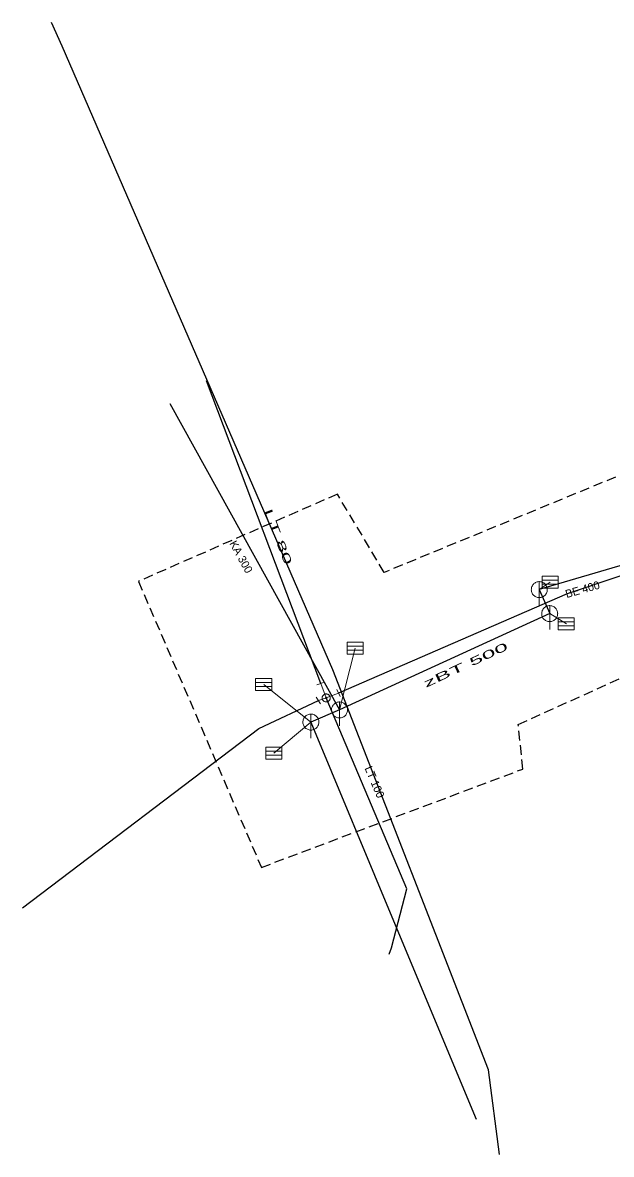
# Model space of a CAD drawing. Extents: x -687387 to -687009, y -972789 to -972578.
# Drawn here: x -687387 to -687313.5, y -972784 to -972642.7 of the extents above; entities that cross this region are included whole.
import ezdxf

# ---------------------------------------------------------------- set-up
doc = ezdxf.new("R2010")
doc.units = 0
doc.header["$LTSCALE"] = 0.4
doc.linetypes.add('MEDIUM_DASHED', pattern=[4.5, 3, -1.5])
doc.layers.add('1', color=7, linetype='Continuous')
for name, color, linetype, lineweight in [('11', 7, 'Continuous', 13), ('14', 7, 'Continuous', 25), ('17', 7, 'Continuous', 25), ('22', 7, 'Continuous', 13), ('34', 7, 'Continuous', 13), ('47', 7, 'Continuous', 13), ('63', 7, 'MEDIUM_DASHED', 25)]:
    doc.layers.add(name, color=color, linetype=linetype, lineweight=lineweight)

msp = doc.modelspace()

# ---------------------------------------------------------------- linework, layer by layer
at = {"layer": '11'}
for p, q in [((-687321.129, -972712.545), (-687322.482, -972713.486)), ((-687319.098, -972717.753), (-687321.188, -972716.487)), ((-687345.471, -972720.82), (-687347.44, -972728.52)), ((-687356.905, -972725.343), (-687351.02, -972730.03)), ((-687355.64, -972733.905), (-687351.02, -972730.03))]:
    msp.add_line(p, q, dxfattribs=at)
at = {"layer": '14'}
for p, q in [((-687368.649, -972690.243), (-687347.44, -972728.52)), ((-687311, -972710.109), (-687322.482, -972713.486)), ((-687322.482, -972713.486), (-687321.188, -972716.487)), ((-687321.188, -972716.487), (-687347.44, -972728.52)), ((-687347.44, -972728.52), (-687351.02, -972730.03))]:
    msp.add_line(p, q, dxfattribs=at)
at = {"layer": '14', "lineweight": 13}
msp.add_line((-687349.109, -972727.02), (-687347.571, -972726.403), dxfattribs=at)
msp.add_lwpolyline([(-687350.08, -972727.344), (-687349.109, -972727.02), (-687349.785, -972725.226)], dxfattribs=at)
at = {"layer": '14'}
msp.add_lwpolyline([(-687351.02, -972730.03), (-687340.476, -972755.348), (-687330.362, -972779.636)], dxfattribs=at)
at = {"layer": '17'}
msp.add_line((-687349.785, -972725.226), (-687364.052, -972687.396), dxfattribs=at)
for points in [[(-687327.469, -972784.025), (-687328.848, -972773.48), (-687348.283, -972723.514), (-687382.078, -972645.626), (-687383.429, -972642.673)], [(-687288.604, -972703.811), (-687319.02, -972714.015), (-687347.571, -972726.403)], [(-687387.027, -972753.222), (-687357.518, -972730.819), (-687350.08, -972727.344)], [(-687341.227, -972759.019), (-687340.943, -972758.234), (-687339.032, -972750.864), (-687349.109, -972727.02)]]:
    msp.add_lwpolyline(points, dxfattribs=at)
at = {"layer": '22'}
for p, q in [((-687322.14, -972712.288), (-687320.14, -972712.288)), ((-687322.482, -972715.486), (-687322.481, -972712.486)), ((-687322.14, -972712.788), (-687320.14, -972712.788)), ((-687321.188, -972718.487), (-687321.187, -972715.487)), ((-687320.109, -972717.496), (-687318.109, -972717.496)), ((-687320.109, -972717.996), (-687318.109, -972717.996)), ((-687346.482, -972720.563), (-687344.482, -972720.563)), ((-687346.482, -972721.063), (-687344.482, -972721.063)), ((-687357.916, -972725.086), (-687355.916, -972725.086)), ((-687357.916, -972725.586), (-687355.916, -972725.586)), ((-687347.44, -972730.52), (-687347.439, -972727.52)), ((-687351.02, -972732.03), (-687351.019, -972729.03)), ((-687356.651, -972733.648), (-687354.651, -972733.648)), ((-687356.651, -972734.148), (-687354.651, -972734.148))]:
    msp.add_line(p, q, dxfattribs=at)
for points in [[(-687322.14, -972711.788), (-687320.14, -972711.788), (-687320.14, -972713.288), (-687322.14, -972713.288)], [(-687321.482, -972713.486), (-687321.487, -972713.377), (-687321.505, -972713.269), (-687321.535, -972713.163), (-687321.575, -972713.062), (-687321.627, -972712.965), (-687321.689, -972712.875), (-687321.761, -972712.792), (-687321.841, -972712.718), (-687321.929, -972712.652), (-687322.023, -972712.597), (-687322.123, -972712.552), (-687322.228, -972712.519), (-687322.335, -972712.497), (-687322.444, -972712.487), (-687322.554, -972712.489), (-687322.662, -972712.503), (-687322.769, -972712.528), (-687322.872, -972712.565), (-687322.97, -972712.614), (-687323.062, -972712.672), (-687323.148, -972712.741), (-687323.225, -972712.818), (-687323.294, -972712.904), (-687323.353, -972712.996), (-687323.401, -972713.094), (-687323.438, -972713.197), (-687323.464, -972713.304), (-687323.478, -972713.412), (-687323.481, -972713.522), (-687323.471, -972713.631), (-687323.45, -972713.738), (-687323.416, -972713.842), (-687323.372, -972713.942), (-687323.317, -972714.037), (-687323.251, -972714.125), (-687323.177, -972714.205), (-687323.094, -972714.277), (-687323.004, -972714.339), (-687322.908, -972714.391), (-687322.806, -972714.432), (-687322.701, -972714.462), (-687322.593, -972714.48), (-687322.483, -972714.486), (-687322.374, -972714.48), (-687322.266, -972714.462), (-687322.161, -972714.433), (-687322.059, -972714.392), (-687321.962, -972714.34), (-687321.872, -972714.278), (-687321.789, -972714.207), (-687321.714, -972714.127), (-687321.649, -972714.039), (-687321.593, -972713.945), (-687321.549, -972713.845), (-687321.515, -972713.741), (-687321.493, -972713.633), (-687321.483, -972713.524)], [(-687320.188, -972716.487), (-687320.193, -972716.378), (-687320.211, -972716.27), (-687320.241, -972716.164), (-687320.281, -972716.063), (-687320.333, -972715.966), (-687320.395, -972715.876), (-687320.467, -972715.793), (-687320.547, -972715.719), (-687320.635, -972715.653), (-687320.729, -972715.598), (-687320.829, -972715.553), (-687320.934, -972715.52), (-687321.041, -972715.498), (-687321.15, -972715.488), (-687321.26, -972715.49), (-687321.368, -972715.504), (-687321.475, -972715.529), (-687321.578, -972715.566), (-687321.676, -972715.615), (-687321.768, -972715.673), (-687321.854, -972715.742), (-687321.931, -972715.819), (-687322, -972715.905), (-687322.059, -972715.997), (-687322.107, -972716.095), (-687322.144, -972716.198), (-687322.17, -972716.305), (-687322.184, -972716.413), (-687322.187, -972716.523), (-687322.177, -972716.632), (-687322.156, -972716.739), (-687322.122, -972716.843), (-687322.078, -972716.943), (-687322.023, -972717.038), (-687321.957, -972717.126), (-687321.883, -972717.206), (-687321.8, -972717.278), (-687321.71, -972717.34), (-687321.614, -972717.392), (-687321.512, -972717.433), (-687321.407, -972717.463), (-687321.299, -972717.481), (-687321.189, -972717.487), (-687321.08, -972717.481), (-687320.972, -972717.463), (-687320.867, -972717.434), (-687320.765, -972717.393), (-687320.668, -972717.341), (-687320.578, -972717.279), (-687320.495, -972717.208), (-687320.42, -972717.128), (-687320.355, -972717.04), (-687320.299, -972716.946), (-687320.255, -972716.846), (-687320.221, -972716.742), (-687320.199, -972716.634), (-687320.189, -972716.525)], [(-687320.109, -972716.996), (-687318.109, -972716.996), (-687318.109, -972718.496), (-687320.109, -972718.496)], [(-687346.482, -972720.063), (-687344.482, -972720.063), (-687344.482, -972721.563), (-687346.482, -972721.563)], [(-687357.916, -972724.586), (-687355.916, -972724.586), (-687355.916, -972726.086), (-687357.916, -972726.086)], [(-687346.44, -972728.52), (-687346.445, -972728.411), (-687346.463, -972728.303), (-687346.493, -972728.197), (-687346.533, -972728.096), (-687346.585, -972727.999), (-687346.647, -972727.909), (-687346.719, -972727.826), (-687346.799, -972727.752), (-687346.887, -972727.686), (-687346.981, -972727.631), (-687347.081, -972727.586), (-687347.186, -972727.553), (-687347.293, -972727.531), (-687347.402, -972727.521), (-687347.512, -972727.523), (-687347.62, -972727.537), (-687347.727, -972727.562), (-687347.83, -972727.599), (-687347.928, -972727.648), (-687348.02, -972727.706), (-687348.106, -972727.775), (-687348.183, -972727.852), (-687348.252, -972727.938), (-687348.311, -972728.03), (-687348.359, -972728.128), (-687348.396, -972728.231), (-687348.422, -972728.338), (-687348.436, -972728.446), (-687348.439, -972728.556), (-687348.429, -972728.665), (-687348.408, -972728.772), (-687348.374, -972728.876), (-687348.33, -972728.976), (-687348.275, -972729.071), (-687348.209, -972729.159), (-687348.135, -972729.239), (-687348.052, -972729.311), (-687347.962, -972729.373), (-687347.866, -972729.425), (-687347.764, -972729.466), (-687347.659, -972729.496), (-687347.551, -972729.514), (-687347.441, -972729.52), (-687347.332, -972729.514), (-687347.224, -972729.496), (-687347.119, -972729.467), (-687347.017, -972729.426), (-687346.92, -972729.374), (-687346.83, -972729.312), (-687346.747, -972729.241), (-687346.672, -972729.161), (-687346.607, -972729.073), (-687346.551, -972728.979), (-687346.507, -972728.879), (-687346.473, -972728.775), (-687346.451, -972728.667), (-687346.441, -972728.558)], [(-687350.02, -972730.03), (-687350.025, -972729.921), (-687350.043, -972729.813), (-687350.073, -972729.707), (-687350.113, -972729.606), (-687350.165, -972729.509), (-687350.227, -972729.419), (-687350.299, -972729.336), (-687350.379, -972729.262), (-687350.467, -972729.196), (-687350.561, -972729.141), (-687350.661, -972729.096), (-687350.766, -972729.063), (-687350.873, -972729.041), (-687350.982, -972729.031), (-687351.092, -972729.033), (-687351.2, -972729.047), (-687351.307, -972729.072), (-687351.41, -972729.109), (-687351.508, -972729.158), (-687351.6, -972729.216), (-687351.686, -972729.285), (-687351.763, -972729.362), (-687351.832, -972729.448), (-687351.891, -972729.54), (-687351.939, -972729.638), (-687351.976, -972729.741), (-687352.002, -972729.848), (-687352.016, -972729.956), (-687352.019, -972730.066), (-687352.009, -972730.175), (-687351.988, -972730.282), (-687351.954, -972730.386), (-687351.91, -972730.486), (-687351.855, -972730.581), (-687351.789, -972730.669), (-687351.715, -972730.749), (-687351.632, -972730.821), (-687351.542, -972730.883), (-687351.446, -972730.935), (-687351.344, -972730.976), (-687351.239, -972731.006), (-687351.131, -972731.024), (-687351.021, -972731.03), (-687350.912, -972731.024), (-687350.804, -972731.006), (-687350.699, -972730.977), (-687350.597, -972730.936), (-687350.5, -972730.884), (-687350.41, -972730.822), (-687350.327, -972730.751), (-687350.252, -972730.671), (-687350.187, -972730.583), (-687350.131, -972730.489), (-687350.087, -972730.389), (-687350.053, -972730.285), (-687350.031, -972730.177), (-687350.021, -972730.068)], [(-687356.651, -972733.148), (-687354.651, -972733.148), (-687354.651, -972734.648), (-687356.651, -972734.648)]]:
    msp.add_lwpolyline(points, close=True, dxfattribs=at)
at = {"layer": '34'}
for p, q in [((-687349.313, -972725.059), (-687350.256, -972725.391)), ((-687347.782, -972725.95), (-687347.359, -972726.856)), ((-687350.363, -972726.932), (-687349.797, -972727.756))]:
    msp.add_line(p, q, dxfattribs=at)
at = {"layer": '47'}
for points in [[(-687348.763, -972727.381), (-687348.728, -972727.343), (-687348.696, -972727.301), (-687348.669, -972727.257), (-687348.646, -972727.21), (-687348.629, -972727.16), (-687348.617, -972727.109), (-687348.611, -972727.057), (-687348.61, -972727.005), (-687348.613, -972726.953), (-687348.623, -972726.901), (-687348.638, -972726.851), (-687348.659, -972726.803), (-687348.683, -972726.757), (-687348.713, -972726.714), (-687348.747, -972726.674), (-687348.785, -972726.639), (-687348.827, -972726.607), (-687348.872, -972726.579), (-687348.918, -972726.557), (-687348.968, -972726.54), (-687349.019, -972726.528), (-687349.072, -972726.521), (-687349.124, -972726.52), (-687349.176, -972726.524), (-687349.227, -972726.534), (-687349.277, -972726.549), (-687349.326, -972726.569), (-687349.371, -972726.594), (-687349.414, -972726.624), (-687349.454, -972726.658), (-687349.489, -972726.696), (-687349.521, -972726.738), (-687349.549, -972726.782), (-687349.571, -972726.829), (-687349.588, -972726.879), (-687349.601, -972726.93), (-687349.608, -972726.982), (-687349.609, -972727.034), (-687349.604, -972727.087), (-687349.594, -972727.138), (-687349.579, -972727.188), (-687349.56, -972727.236), (-687349.534, -972727.282), (-687349.504, -972727.325), (-687349.47, -972727.365), (-687349.432, -972727.4), (-687349.39, -972727.432), (-687349.346, -972727.46), (-687349.299, -972727.482), (-687349.249, -972727.499), (-687349.198, -972727.512), (-687349.147, -972727.518), (-687349.094, -972727.519), (-687349.042, -972727.515), (-687348.99, -972727.505), (-687348.94, -972727.49), (-687348.892, -972727.47), (-687348.846, -972727.445), (-687348.803, -972727.415)], [(-687349.052, -972727.079), (-687349.045, -972727.073), (-687349.041, -972727.066), (-687349.037, -972727.059), (-687349.033, -972727.051), (-687349.03, -972727.043), (-687349.028, -972727.034), (-687349.027, -972727.026), (-687349.026, -972727.017), (-687349.028, -972727.009), (-687349.029, -972727), (-687349.031, -972726.992), (-687349.035, -972726.984), (-687349.039, -972726.977), (-687349.043, -972726.969), (-687349.049, -972726.963), (-687349.055, -972726.956), (-687349.062, -972726.952), (-687349.069, -972726.948), (-687349.077, -972726.944), (-687349.085, -972726.941), (-687349.094, -972726.939), (-687349.102, -972726.938), (-687349.111, -972726.937), (-687349.12, -972726.938), (-687349.128, -972726.94), (-687349.136, -972726.942), (-687349.144, -972726.946), (-687349.151, -972726.95), (-687349.159, -972726.954), (-687349.165, -972726.96), (-687349.172, -972726.966), (-687349.176, -972726.973), (-687349.18, -972726.98), (-687349.184, -972726.988), (-687349.187, -972726.996), (-687349.189, -972727.004), (-687349.19, -972727.013), (-687349.191, -972727.022), (-687349.19, -972727.031), (-687349.188, -972727.039), (-687349.186, -972727.047), (-687349.182, -972727.055), (-687349.178, -972727.062), (-687349.174, -972727.07), (-687349.168, -972727.076), (-687349.162, -972727.083), (-687349.155, -972727.087), (-687349.148, -972727.091), (-687349.14, -972727.095), (-687349.132, -972727.098), (-687349.124, -972727.1), (-687349.115, -972727.101), (-687349.106, -972727.102), (-687349.098, -972727.1), (-687349.089, -972727.099), (-687349.081, -972727.097), (-687349.073, -972727.093), (-687349.066, -972727.089), (-687349.058, -972727.085)]]:
    msp.add_lwpolyline(points, close=True, dxfattribs=at)
at = {"layer": '63'}
msp.add_lwpolyline([(-687147.303, -972666.399), (-687234.11, -972667.795), (-687234.11, -972667.795), (-687256.998, -972673.098), (-687256.998, -972673.098), (-687289.655, -972689.845), (-687289.655, -972689.845), (-687341.85, -972711.338), (-687341.85, -972711.338), (-687347.712, -972701.568), (-687347.712, -972701.568), (-687372.554, -972712.454), (-687357.202, -972748.182), (-687357.202, -972748.182), (-687324.545, -972735.9), (-687324.545, -972735.9), (-687325.103, -972730.318), (-687325.103, -972730.318), (-687291.05, -972714.966), (-687291.05, -972714.966), (-687198.94, -972690.124), (-687198.94, -972690.124), (-687142.558, -972685.938)], dxfattribs=at)

# ---------------------------------------------------------------- texts
at = {"layer": '1'}
for s, rotation, width, p in [('LT 80 ', 291, 2.15, (-687356.879, -972703.624)), ('zBT 500 ', 25, 2.3, (-687336.668, -972725.766))]:
    msp.add_text(s, height=1, rotation=rotation, dxfattribs=dict(at, width=width)).set_placement(p)
for s, rotation, p in [('KA 300', 299, (-687361.234, -972707.719)), ('BE 400', 16, (-687319.059, -972714.549)), ('LT 100', 293, (-687344.33, -972735.795))]:
    msp.add_text(s, height=1, rotation=rotation, dxfattribs=at).set_placement(p)

doc.saveas('drawing.dxf')
